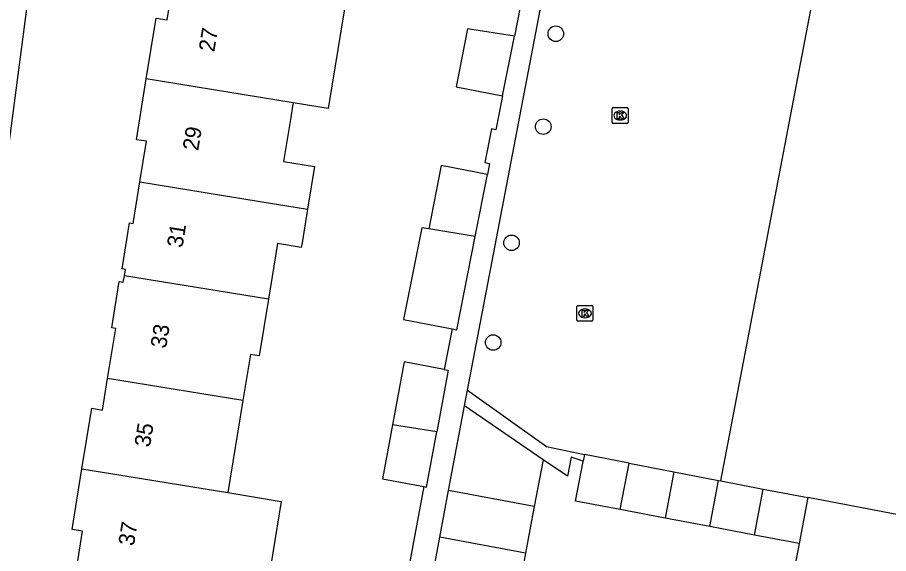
# Model space of a CAD drawing. Extents: x 161402 to 161933, y 381650 to 382313.
# Drawn here: x 161806.7 to 161861.5, y 381882.3 to 381916 of the extents above; entities that cross this region are included whole.
import ezdxf

# ---------------------------------------------------------------- set-up
doc = ezdxf.new("R2010")
doc.units = 0
for name, color, linetype in [('IMGEO_Boom', 7, 'Continuous'), ('IMGEO_Kolk', 7, 'Continuous'), ('IMGEO_Muur', 7, 'Continuous'), ('IMGEO_Pand', 7, 'Continuous'), ('IMGEO_Pand_nummerreeks', 7, 'Continuous'), ('IMGEO_Voetpad_open', 7, 'Continuous')]:
    doc.layers.add(name, color=color, linetype=linetype)

msp = doc.modelspace()

# ---------------------------------------------------------------- linework, layer by layer
at = {"layer": 'IMGEO_Boom'}
for centre in [(161840.551, 381914.984), (161839.764, 381909.146), (161837.77, 381901.846), (161836.618, 381895.58)]:
    msp.add_circle(centre, 0.489, dxfattribs=at)
at = {"layer": 'IMGEO_Kolk'}
for p, q in [((161844.094, 381909.419), (161844.094, 381910.271)), ((161844.169, 381910.345), (161845.021, 381910.345)), ((161844.582, 381910.125), (161844.607, 381910.125)), ((161845.095, 381910.271), (161845.095, 381909.419)), ((161845.021, 381909.345), (161844.169, 381909.345)), ((161844.605, 381909.565), (161844.58, 381909.565)), ((161841.881, 381896.989), (161841.881, 381897.841)), ((161841.956, 381897.915), (161842.808, 381897.915)), ((161842.882, 381897.841), (161842.882, 381896.989)), ((161842.369, 381897.695), (161842.394, 381897.695)), ((161842.808, 381896.915), (161841.956, 381896.915)), ((161842.392, 381897.135), (161842.367, 381897.135))]:
    msp.add_line(p, q, dxfattribs=at)
for points in [[(161844.094, 381909.419), (161844.094, 381910.271)], [(161844.169, 381910.345), (161845.021, 381910.345)], [(161844.415, 381910.045), (161844.538, 381910.045), (161844.538, 381909.894), (161844.668, 381910.045), (161844.832, 381910.045), (161844.686, 381909.894), (161844.839, 381909.645), (161844.687, 381909.645), (161844.602, 381909.809), (161844.538, 381909.742), (161844.538, 381909.645), (161844.415, 381909.645), (161844.415, 381910.045)], [(161845.095, 381910.271), (161845.095, 381909.419)], [(161845.021, 381909.345), (161844.169, 381909.345)], [(161841.881, 381896.989), (161841.881, 381897.841)], [(161841.956, 381897.915), (161842.808, 381897.915)], [(161842.882, 381897.841), (161842.882, 381896.989)], [(161842.202, 381897.615), (161842.325, 381897.615), (161842.325, 381897.464), (161842.455, 381897.615), (161842.619, 381897.615), (161842.473, 381897.464), (161842.626, 381897.215), (161842.474, 381897.215), (161842.389, 381897.379), (161842.325, 381897.312), (161842.325, 381897.215), (161842.202, 381897.215), (161842.202, 381897.615)], [(161842.808, 381896.915), (161841.956, 381896.915)]]:
    msp.add_lwpolyline(points, dxfattribs=at)
for centre, start, end in [((161844.171, 381910.269), 91.552, 178.448), ((161844.171, 381910.269), 91.552, 178.448), ((161845.019, 381910.269), 1.552, 88.448), ((161845.019, 381910.269), 1.552, 88.448), ((161844.171, 381909.421), 181.552, 268.448), ((161844.171, 381909.421), 181.552, 268.448), ((161845.019, 381909.421), 271.552, 358.448), ((161845.019, 381909.421), 271.552, 358.448), ((161841.958, 381897.839), 91.552, 178.448), ((161841.958, 381897.839), 91.552, 178.448), ((161842.806, 381897.839), 1.552, 88.448), ((161842.806, 381897.839), 1.552, 88.448), ((161841.958, 381896.991), 181.552, 268.448), ((161841.958, 381896.991), 181.552, 268.448), ((161842.806, 381896.991), 271.552, 358.448), ((161842.806, 381896.991), 271.552, 358.448)]:
    msp.add_arc(centre, 0.0765, start, end, dxfattribs=at)
for centre, major_axis, ratio, start_param, end_param in [((161844.581, 381909.845), (-0.387, 0.002), 0.722429, 4.712389, 7.853982), ((161844.606, 381909.845), (-0.39, 0.002), 0.717154, 1.570796, 4.712389), ((161842.368, 381897.415), (-0.387, 0.002), 0.722429, 4.712389, 7.853982), ((161842.393, 381897.415), (-0.39, 0.002), 0.717154, 1.570796, 4.712389)]:
    msp.add_ellipse(centre, major_axis=major_axis, ratio=ratio, start_param=start_param, end_param=end_param, dxfattribs=at)
at = {"layer": 'IMGEO_Muur'}
for points in [[(161834.817, 381891.606), (161835.006, 381892.594)], [(161835.006, 381892.594), (161839.967, 381889.053), (161842.348, 381888.535)], [(161842.271, 381888.132), (161841.509, 381888.382), (161841.29, 381887.172), (161839.754, 381888.208)]]:
    msp.add_lwpolyline(points, dxfattribs=at)
at = {"layer": 'IMGEO_Pand'}
for points in [[(161850.925, 381886.881), (161857.717, 381922.54), (161857.498, 381922.591)], [(161814.828, 381912.15), (161815.451, 381915.973), (161816.136, 381915.861), (161816.533, 381918.296)], [(161827.279, 381916.551), (161826.26, 381910.293), (161824.053, 381910.652)], [(161837.95, 381914.826), (161835.012, 381915.303), (161834.294, 381911.658), (161837.212, 381911.083)], [(161837.212, 381911.083), (161837.95, 381914.826)], [(161814.419, 381905.67), (161814.835, 381908.224), (161814.206, 381908.327), (161814.828, 381912.15)], [(161824.053, 381910.652), (161814.828, 381912.15)], [(161824.053, 381910.652), (161824.019, 381910.443), (161823.902, 381909.727), (161823.452, 381906.959), (161825.393, 381906.643), (161824.956, 381903.959)], [(161836.253, 381906.136), (161833.35, 381906.708), (161832.565, 381902.723)], [(161835.487, 381902.249), (161836.253, 381906.136)], [(161813.451, 381899.77), (161813.516, 381900.172), (161813.306, 381900.207), (161813.776, 381903.091), (161813.993, 381903.056), (161814.419, 381905.67)], [(161814.419, 381905.67), (161823.015, 381904.274), (161824.956, 381903.959)], [(161824.956, 381903.959), (161824.611, 381901.837), (161824.565, 381901.554), (161823.073, 381901.8), (161822.503, 381898.3)], [(161832.565, 381902.723), (161832.128, 381902.796), (161830.993, 381897.036), (161834.039, 381896.435)], [(161835.487, 381902.249), (161832.565, 381902.723)], [(161834.039, 381896.435), (161834.33, 381896.378), (161835.487, 381902.249)], [(161812.401, 381893.32), (161812.914, 381896.467), (161812.659, 381896.508), (161813.131, 381899.41), (161813.385, 381899.368), (161813.451, 381899.77)], [(161822.503, 381898.3), (161813.451, 381899.77)], [(161822.503, 381898.3), (161821.924, 381894.745), (161821.371, 381894.835), (161820.9, 381891.94)], [(161833.538, 381893.893), (161831.029, 381894.361), (161830.293, 381890.415)], [(161833.538, 381893.893), (161833.795, 381893.845), (161833.071, 381889.964)], [(161810.785, 381887.636), (161811.405, 381891.443), (161812.078, 381891.334), (161812.401, 381893.32)], [(161820.9, 381891.94), (161812.401, 381893.32)], [(161820.9, 381891.94), (161819.956, 381886.143)], [(161833.816, 381886.284), (161834.817, 381891.606)], [(161839.754, 381888.208), (161834.817, 381891.606)], [(161830.293, 381890.415), (161829.659, 381887.011), (161832.263, 381886.525)], [(161833.071, 381889.964), (161830.293, 381890.415)], [(161832.263, 381886.525), (161832.425, 381886.495), (161833.071, 381889.964)], [(161842.348, 381888.535), (161842.271, 381888.132)], [(161845.156, 381887.993), (161842.348, 381888.535)], [(161839.754, 381888.208), (161839.201, 381885.271)], [(161844.601, 381885.08), (161841.792, 381885.615), (161842.264, 381888.093), (161842.271, 381888.132)], [(161844.601, 381885.08), (161845.156, 381887.993)], [(161845.156, 381887.993), (161847.965, 381887.452)], [(161810.395, 381881.067), (161810.826, 381883.715), (161810.164, 381883.823), (161810.785, 381887.636)], [(161810.785, 381887.636), (161819.956, 381886.143)], [(161847.965, 381887.452), (161847.411, 381884.544)], [(161847.965, 381887.452), (161850.773, 381886.91)], [(161850.22, 381884.009), (161850.773, 381886.91)], [(161850.773, 381886.91), (161850.925, 381886.881)], [(161850.925, 381886.881), (161853.582, 381886.372)], [(161853.03, 381883.473), (161853.582, 381886.372)], [(161853.582, 381886.372), (161856.391, 381885.835)], [(161819.956, 381886.143), (161823.31, 381885.597), (161822.259, 381879.139), (161818.905, 381879.685)], [(161833.265, 381883.355), (161833.816, 381886.284)], [(161839.201, 381885.271), (161833.816, 381886.284)], [(161856.391, 381885.835), (161855.839, 381882.938)], [(161874.777, 381882.317), (161856.391, 381885.835)], [(161839.201, 381885.271), (161838.65, 381882.342)], [(161847.411, 381884.544), (161844.601, 381885.08)], [(161850.22, 381884.009), (161847.411, 381884.544)], [(161853.03, 381883.473), (161850.22, 381884.009)], [(161832.714, 381880.427), (161833.265, 381883.355)], [(161838.65, 381882.342), (161833.265, 381883.355)], [(161855.839, 381882.938), (161853.03, 381883.473)], [(161855.839, 381882.938), (161853.748, 381871.965), (161859.14, 381870.938)], [(161838.65, 381882.342), (161838.099, 381879.413)]]:
    msp.add_lwpolyline(points, dxfattribs=at)
at = {"layer": 'IMGEO_Voetpad_open'}
for points in [[(161778.698, 381768.78), (161781.039, 381777.203), (161788.629, 381808.145), (161791.311, 381819.878), (161794.918, 381837.231), (161795.748, 381841.221), (161796.717, 381845.885), (161801.214, 381871.562), (161802.683, 381881.227), (161808.066, 381922.168), (161810.3, 381942.403)], [(161841.338, 381933.465), (161841.004, 381931.771), (161841.413, 381931.69), (161840.509, 381927.103), (161839.352, 381921.234), (161838.943, 381921.315), (161838.579, 381919.466), (161838.854, 381919.412), (161838.634, 381918.295), (161837.95, 381914.826)], [(161835.006, 381892.594), (161842.669, 381932.702)], [(161837.212, 381911.083), (161836.793, 381908.956), (161836.518, 381909.01), (161836.1, 381906.892), (161836.391, 381906.835), (161836.253, 381906.136)], [(161834.039, 381896.435), (161833.538, 381893.893)], [(161832.263, 381886.525), (161831.343, 381881.592)]]:
    msp.add_lwpolyline(points, dxfattribs=at)

# ---------------------------------------------------------------- texts
at = {"layer": 'IMGEO_Pand_nummerreeks'}
for s, rotation, p in [('27', 80.7584, (161819.097, 381913.801)), ('29', 80.7584, (161818.087, 381907.592)), ('31', 80.7584, (161817.096, 381901.495)), ('33', 80.7599, (161816.067, 381895.173)), ('35', 80.7599, (161815.057, 381888.964)), ('37', 80.7599, (161814.046, 381882.754))]:
    msp.add_text(s, height=1, rotation=rotation, dxfattribs=at).set_placement(p)

doc.saveas('drawing.dxf')
